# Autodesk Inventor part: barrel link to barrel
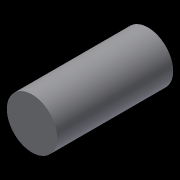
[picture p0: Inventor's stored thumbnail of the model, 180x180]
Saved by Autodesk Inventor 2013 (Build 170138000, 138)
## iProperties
Created: 2013-01
Part Number: barrel link to barrel
Material: Generic
Document SubType Name: Modeling
Designer: John
Density: 1 g/cm^3
Author: John
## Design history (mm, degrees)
sketch "Sketch1"
  geometry: C1 r 1.975 at (0, 0); 1 further point
  constraints: 1 centre point, 1 coincident
  dimensions: "d0" = 3.9497 diameter of C1
extrude "Extrusion1" new body sketch "Sketch1" distance "d1" = 9.0932; taper "d2" = 0 deg
body "Solid1"
